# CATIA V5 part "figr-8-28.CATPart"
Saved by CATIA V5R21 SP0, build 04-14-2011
Part number: Part1
Bounding box of the stored display mesh (mm): x 37.5 to 207.5, y 10 to 85, z 0 to 113
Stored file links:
  D:\CATIA V5R21 E-RESOURCES\CATIA-V5R21\catia-v5r21-prt\c08-catia-v5r20-prt\c08-catia-v5r21-figr-8-28.CATPart
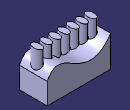
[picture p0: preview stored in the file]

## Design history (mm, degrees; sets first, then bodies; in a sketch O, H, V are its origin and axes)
Set1
  Plane1: type Offset, RefPlane xy-plane, Offset 113
Body1 (main body)
  Sketch1 on xy-plane, origin (0, 0, 0), H (1, 0, 0), V (0, 1, 0)
    line L1 (-37.5, 85) -> (37.5, 85)
    line L2 (37.5, 85) -> (37.5, -85)
    line L3 (37.5, -85) -> (-37.5, -85)
    line L4 (-37.5, -85) -> (-37.5, 85)
    axis line L5 (37.5, -85) -> (-37.5, 85)
    length L3 = 75
    length L2 = 170
    horizontal: L1 H, L3 H
    vertical: L2 V, L4 V
    midpoint: O L5
  Pad1: profile Sketch1, direction (0, 0, 1), length 83
  Sketch2 on face of Pad1, origin (37.5, 0, 0), H (0, 1, 0), V (0, 0, 1)
    spline S1 through (-85, 56.7422) (-58.5369, 80.0687) (-27.7952, 70.201) (85, 83)
    reference projected line E1 (85, 0) -> (85, 83) from edge [face of Pad1 | face of Pad1]
    reference projected line E2 (-85, 0) -> (-85, 83) from edge [face of Pad1 | face of Pad1]
    reference projected line E3 (-85, 83) -> (85, 83) from edge [face of Pad1 | face of Pad1]
    point P1 (85, 83)
    point P3 (-85, 56.7422)
    coincidence: P1 E1, P3 E2, P1 E3
  Pocket1: profile Sketch2, direction (-1, 0, 0), length 83
  Rotate1: Axis edge [face of Pad1 | face of Pad1], Angle 90, ToTransfor Pocket1
  Sketch3 on Plane1, origin (0, 0, 113), H (1, 0, 0), V (0, 1, 0)
    ellipse A1 centre (195.4286, 45.9861) semi-axes 14.9247, 8.8005 rotation 90
  Pad2: profile Sketch3, direction (0, 0, -1), up to face of Pocket1
  RectPattern1: of Pad2, direction 1 instances 7, spacing 24, along edge [face of Pad1 | face of Pad1]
